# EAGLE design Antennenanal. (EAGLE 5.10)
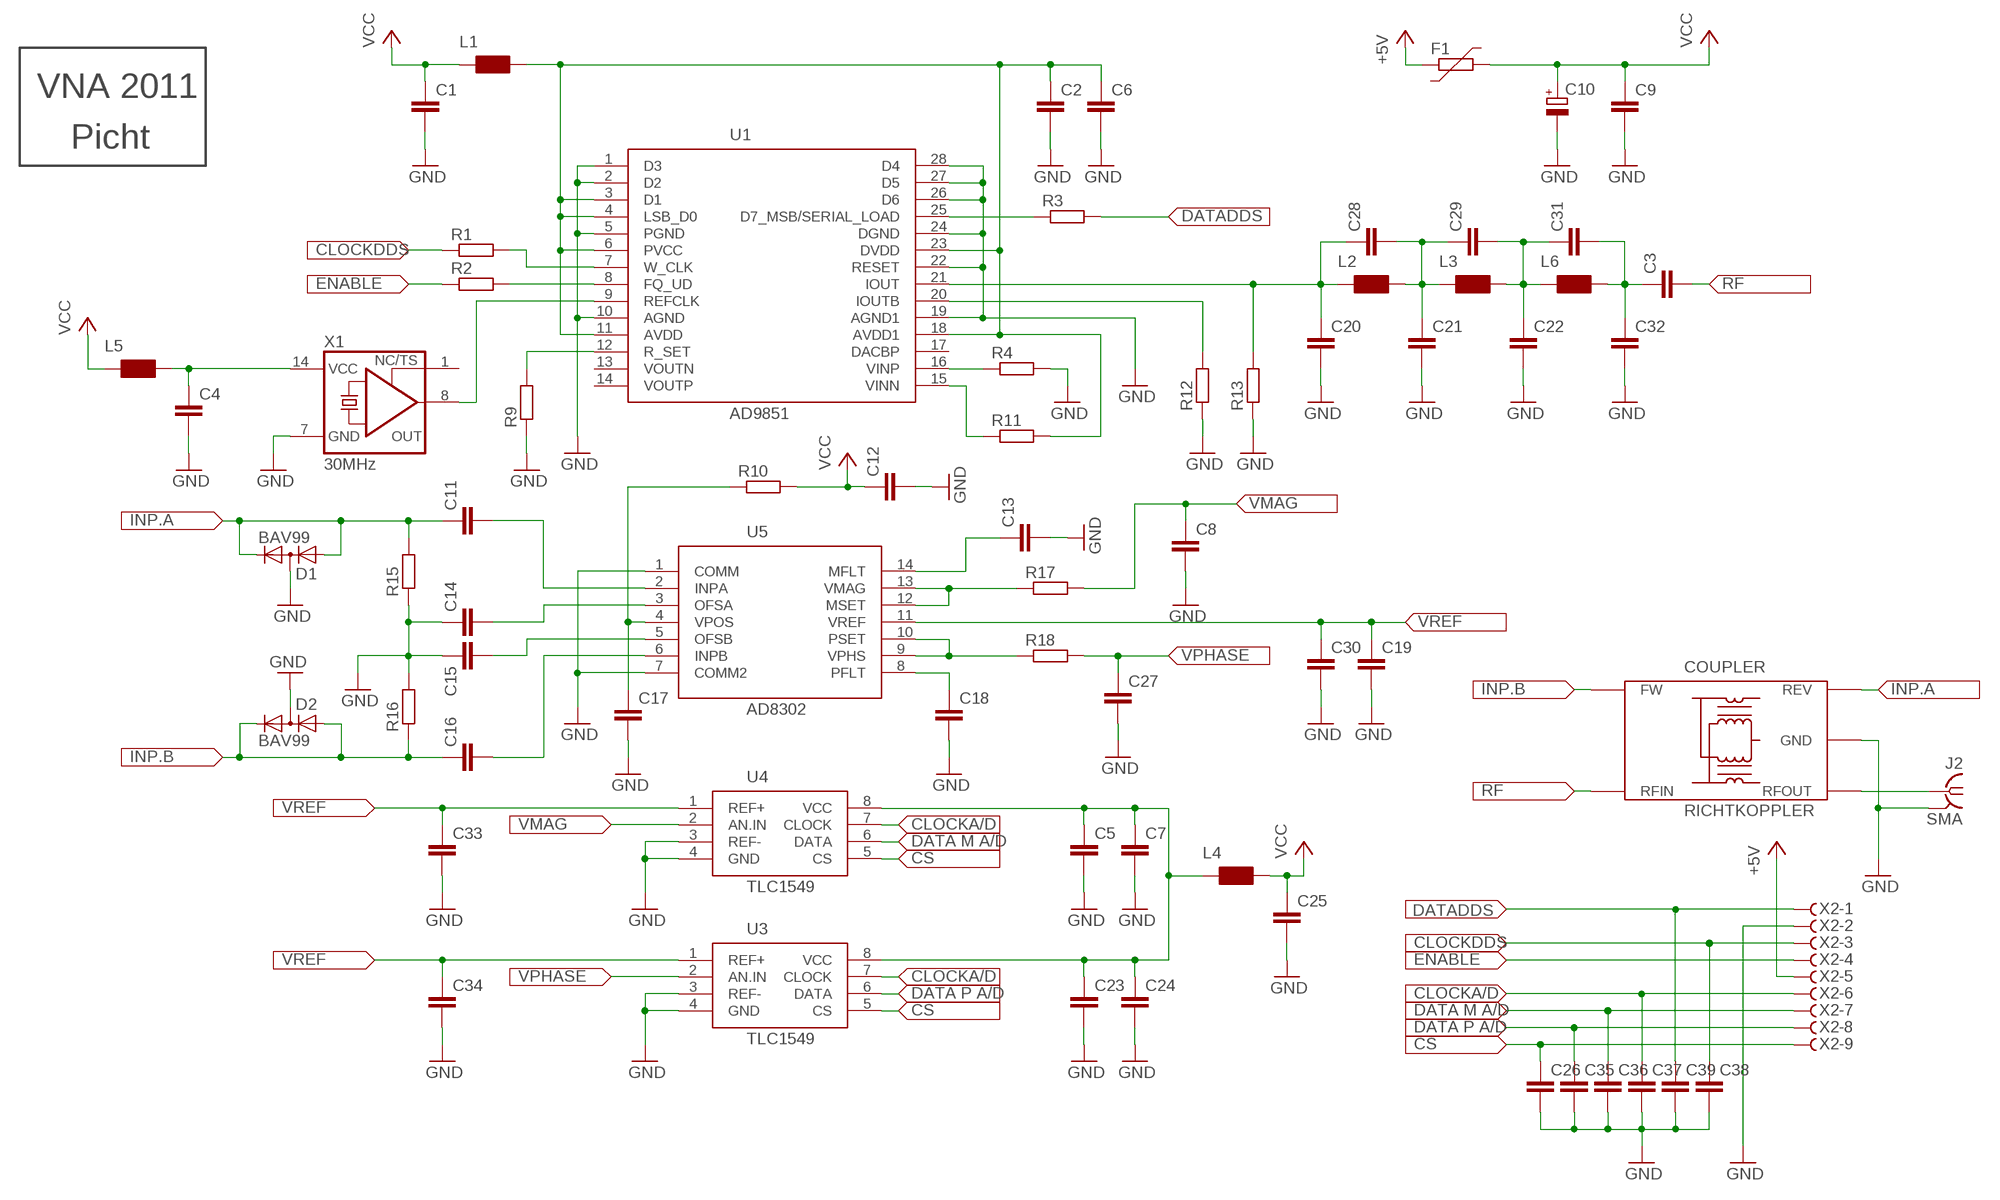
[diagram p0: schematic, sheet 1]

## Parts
C1  C-EUC0805  [C0805]
C2  C-EUC0805  [C0805]
C3  C-EUC0805  [C0805]
C4  C-EUC0805  [C0805]
C5  C-EUC0805  [C0805]
C6  C-EUC0805  [C0805]
C7  C-EUC0805  [C0805]
C8  C-EUC0805  [C0805]
C9  C-EUC0805  [C0805]
C10  CPOL-EU153CLV-0605  [153CLV-0605]
C11  C-EUC0805  [C0805]
C12  C-EUC0805  [C0805]
C13  C-EUC0805  [C0805]
C14  C-EUC0805  [C0805]
C15  C-EUC0805  [C0805]
C16  C-EUC0805  [C0805]
C17  C-EUC0805  [C0805]
C18  C-EUC0805  [C0805]
C19  C-EUC0805  [C0805]
C20  C-EUC0805  [C0805]
C21  C-EUC0805  [C0805]
C22  C-EUC0805  [C0805]
C23  C-EUC0805  [C0805]
C24  C-EUC0805  [C0805]
C25  C-EUC0805  [C0805]
C26  C-EUC0805  [C0805]
C27  C-EUC0805  [C0805]
C28  C-EUC0805  [C0805]
C29  C-EUC0805  [C0805]
C30  C-EUC0805  [C0805]
C31  C-EUC0805  [C0805]
C32  C-EUC0805  [C0805]
C33  C-EUC0805  [C0805]
C34  C-EUC0805  [C0805]
C35  C-EUC0805  [C0805]
C36  C-EUC0805  [C0805]
C37  C-EUC0805  [C0805]
C38  C-EUC0805  [C0805]
C39  C-EUC0805  [C0805]
COUPLER  RICHTKOPPLER  KOPPLER  [KOPPLER]
D1  BAV99  BAV199  [SOT23]
D2  BAV99  BAV199  [SOT23]
F1  R-EU_0204/2V  [0204V]
J2  SMA  SMA-142-0701-851/861  [J502-ND-142-0701-851/861]
L1  IND.1210  [C1210]
L2  IND.1210  [C1210]
L3  IND.1210  [C1210]
L4  IND.1210  [C1210]
L5  IND.1210  [C1210]
L6  IND.1210  [C1210]
R1  R-EU_M1206  [M1206]
R2  R-EU_M1206  [M1206]
R3  R-EU_M1206  [M1206]
R4  R-EU_M1206  [M1206]
R9  R-EU_R1206  [R1206]
R10  R-EU_R1206  [R1206]
R11  R-EU_M1206  [M1206]
R12  R-EU_M1206  [M1206]
R13  R-EU_M1206  [M1206]
R15  R-EU_R1206  [R1206]
R16  R-EU_R1206  [R1206]
R17  R-EU_R1206  [R1206]
R18  R-EU_R1206  [R1206]
U1  AD9851  AD9851BR  [TSSOP28]
U3  TLC1549  [SO8]
U4  TLC1549  [SO8]
U5  AD8302  AD8202  [TSSOP14]
X1  30MHz  XO-14  [DIL14S]
X2  F09HPS  [F09HP]

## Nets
+5V: F1.1 X2.5
CLOCKA/D: C37.1 U3.7(CLOCK) U4.7(CLOCK) X2.6
CLOCKDDS: C38.1 R1.1 X2.3
CS: C26.1 U3.5(CS) U4.5(CS) X2.9
DATA_M_A/D: C36.1 U4.6(DATA) X2.7
DATA_P_A/D: C35.1 U3.6(DATA) X2.8
DATADDS: C39.1 R3.2 X2.1
ENABLE: R2.1 X2.4
GND: C1.2 C2.2 C4.2 C5.2 C6.2 C7.2 C8.2 C9.2 C10.- C12.2 C13.2 C14.1 C15.1 C17.2 C18.2 C19.2 C20.2 C21.2 C22.2 C23.2 C24.2 C25.2 C26.2 C27.2 C30.2 C32.2 C33.2 C34.2 C35.2 C36.2 C37.2 C38.2 C39.2 COUPLER.P$5(GND) D1.3(AC) D2.3(AC) J2.G@1(GND) R4.2 R9.1 R12.1 R13.1 R15.1 R16.2 U1.1(D3) U1.2(D2) U1.5(PGND) U1.10(AGND) U1.19(AGND1) U1.22(RESET) U1.24(DGND) U1.26(D6) U1.27(D5) U1.28(D4) U3.3(REF-) U3.4(GND) U4.3(REF-) U4.4(GND) U5.1(COMM) U5.7(COMM2) X1.7(GND) X2.2
INP.A: C11.1 COUPLER.P$4(REV) D1.1(A) D1.2(C) R15.2
INP.B: C16.1 COUPLER.P$1(FW) D2.1(A) D2.2(C) R16.1
N$1: R12.2 U1.20(IOUTB)
N$2: R1.2 U1.7(W_CLK)
N$3: R2.2 U1.8(FQ_UD)
N$4: R3.1 U1.25(D7_MSB/SERIAL_LOAD)
N$5: R4.1 U1.16(VINP)
N$6: R11.1 U1.15(VINN)
N$7: R9.2 U1.12(R_SET)
N$8: C20.1 C28.1 L2.2 R13.2 U1.21(IOUT)
N$9: C5.1 C7.1 C23.1 C24.1 L4.2 U3.8(VCC) U4.8(VCC)
N$10: C17.1 R10.1 U5.4(VPOS)
N$11: C11.2 U5.2(INPA)
N$12: C21.1 C28.2 C29.1 L2.1(.) L3.2
N$13: C22.1 C29.2 C31.1 L3.1(.) L6.2
N$14: C3.1 C31.2 C32.1 L6.1(.)
N$15: C2.1 C6.1 L1.1(.) R11.2 U1.3(D1) U1.4(LSB_D0) U1.6(PVCC) U1.11(AVDD) U1.18(AVDD1) U1.23(DVDD)
N$16: U1.9(REFCLK) X1.8(OUT)
N$17: C4.1 L5.1(.) X1.14(VCC)
N$18: C13.1 U5.14(MFLT)
N$19: C16.2 U5.6(INPB)
N$20: C18.1 U5.8(PFLT)
N$21: R17.1 U5.12(MSET) U5.13(VMAG)
N$22: COUPLER.P$3(RFOUT) J2.1
N$23: C14.2 U5.3(OFSA)
N$24: R18.1 U5.9(VPHS) U5.10(PSET)
N$25: C15.2 U5.5(OFSB)
RF: C3.2 COUPLER.P$2(RFIN)
VCC: C1.1 C9.1 C10.+ C12.1 C25.1 F1.2 L1.2 L4.1(.) L5.2 R10.2
VMAG: C8.1 R17.2 U4.2(AN.IN)
VPHASE: C27.1 R18.2 U3.2(AN.IN)
VREF: C19.1 C30.1 C33.1 C34.1 U3.1(REF+) U4.1(REF+) U5.11(VREF)
Unconnected: U1.13(VOUTN) U1.14(VOUTP) U1.17(DACBP) X1.1(TS)

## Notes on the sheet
- VNA 2011
- U1
- Picht
- AD9851

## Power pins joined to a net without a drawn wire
GND: J2.G@2(GND) J2.G@3(GND) J2.G@4(GND)

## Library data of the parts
C1-C9 C11-C39 = rcl:C-EU: CAPACITOR, European symbol
C10 = rcl:CPOL-EU: POLARIZED CAPACITOR, European symbol
COUPLER = Koppler:KOPPLER
D1 D2 = diode:BAV199: DIODE low-leakage double diode
F1 R1-R4 R9-R13 R15-R18 = rcl:R-EU_: RESISTOR, European symbol
J2 = con-coax:SMA-: SMA 50 Ohm End Launch Jack Receptacle - Round Contact Johnson Components Source: www.johnsoncomponents.com .. J502-ND.pdf
L1-L6 = Ind.1210:IND.1210
U1 = ad9851:AD9851: DDS
U3 U4 = TLC1549:TLC1549
U5 = AD8302:AD8202
X1 = crystal:XO-: CRYSTAL
X2 = con-subd:F09?S: SUB-D

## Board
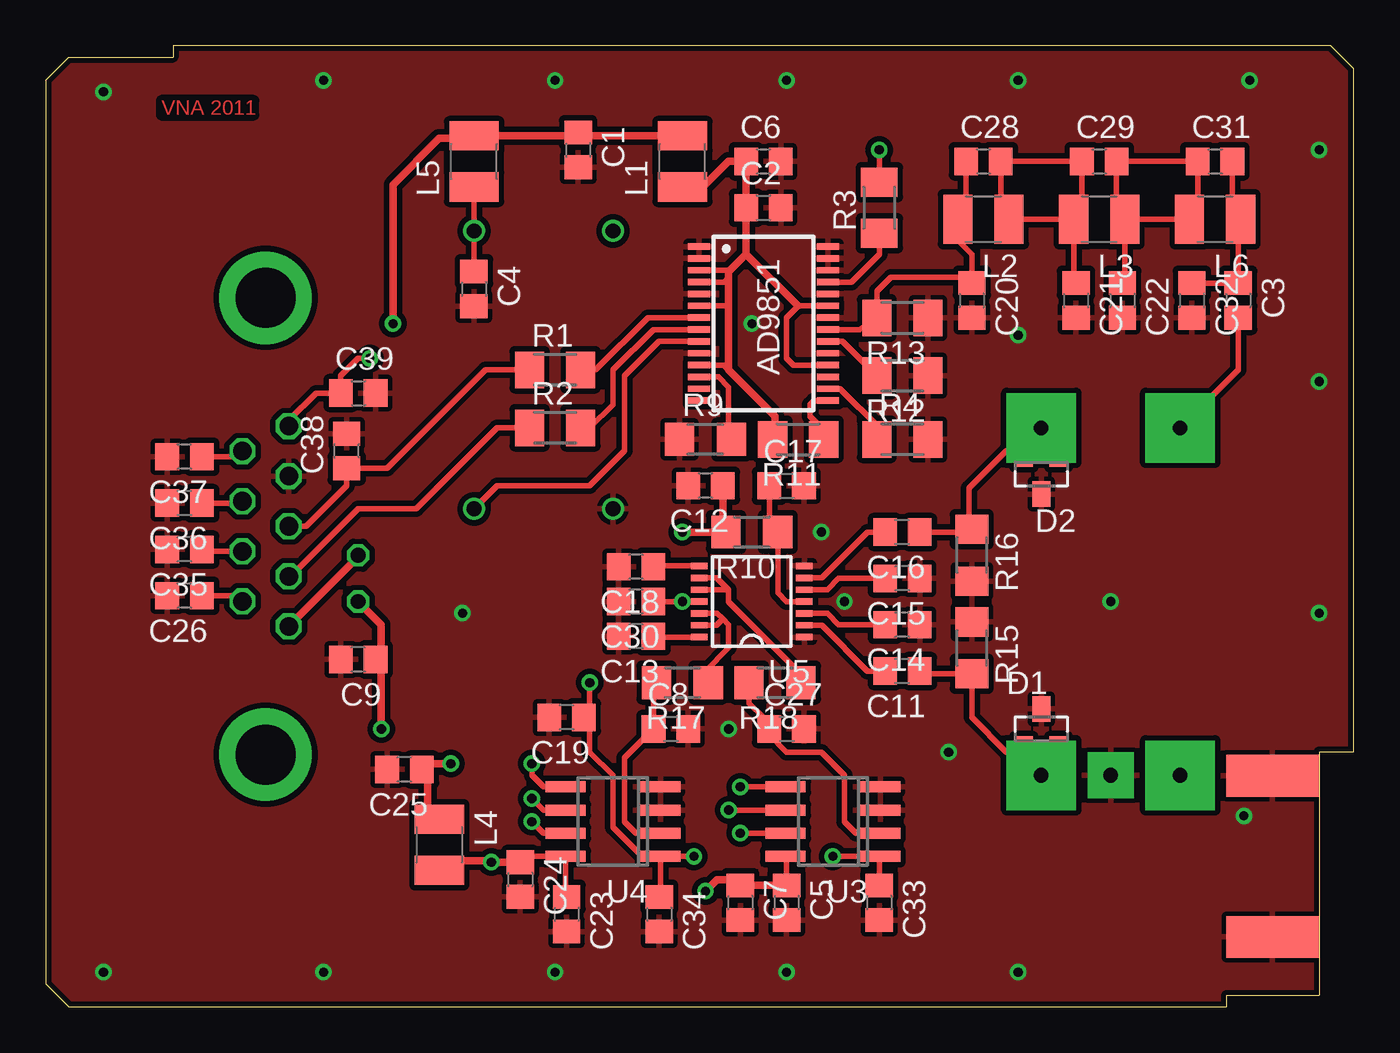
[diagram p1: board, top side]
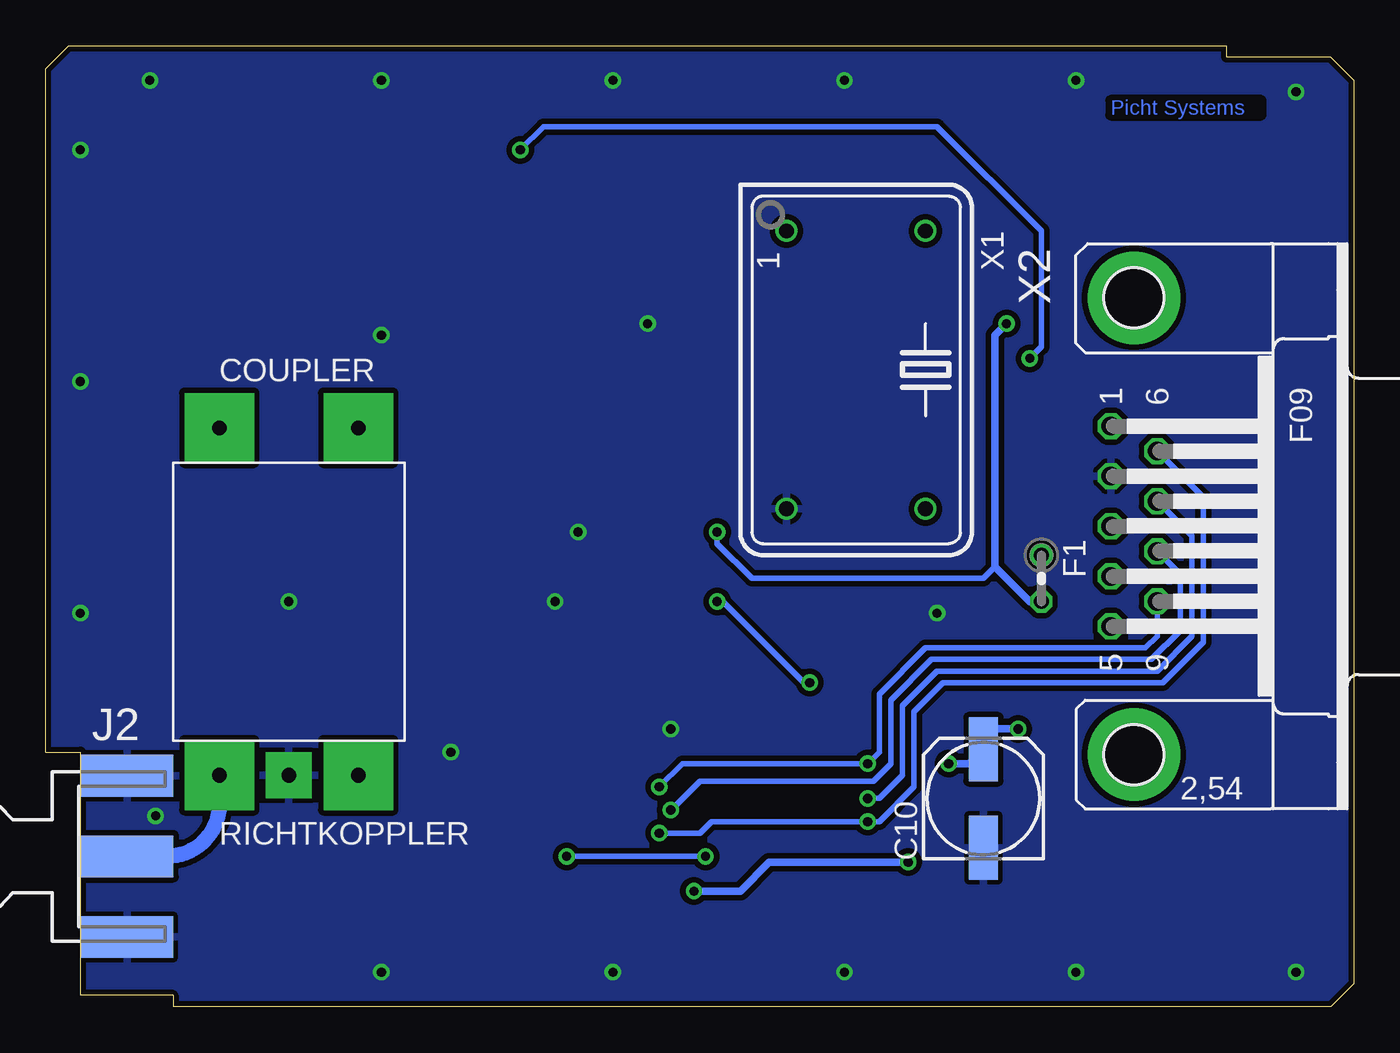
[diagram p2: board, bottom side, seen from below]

Size 71.75 x 52.7 mm. Coordinates in mm from the lower left corner, seen from the top.
Outline: 71.74,51.42 71.74,13.97 69.85,13.97 69.85,0.64 64.77,0.64 64.77,0 1.27,0 0,1.27 0,50.8 1.27,52.07 6.99,52.07 6.99,52.7
Outline: 71.75,51.44 70.48,52.7 6.99,52.7
Copper layers (1*16): Top 0.035mm / dielectric 1.5mm / Bottom 0.035mm
Design rules "ZWILLING": minimum track width 0.2mm, minimum drill 0.5mm, track to track 0.2mm, track to pad 0.2mm, pad to pad 0.15mm, via to via 0.2mm, smd to smd 0mil, copper to edge 0.2mm, drill to drill 0.2mm, minimum pad ring 0.2mm, minimum via ring 0.2mm, stop-mask expansion 0.1mm, vias tented up to drill 0mil, thermal gap 10mil

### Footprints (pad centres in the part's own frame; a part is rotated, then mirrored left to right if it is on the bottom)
C0805 = smd 1.3 x 1.5: 1 -0.95,0; 2 0.95,0
153CLV-0605 = smd 3.5 x 1.6: + 2.7,0; - -2.7,0
KOPPLER = drill 0.8 pad 3.81 square: P$1 3.81,9.525; P$2 -3.81,9.525; P$3 -3.81,-9.525; P$4 3.81,-9.525 | drill 0.8 pad 2.54 square: P$5 0,-9.525
SOT23 = smd 1 x 1.4: 1 -0.95,-1.1; 2 0.95,-1.1; 3 0,1.1
0204V = drill 0.813 octagon: 1 -1.27,0; 2 1.27,0
J502-ND-142-0701-851/861 = smd 5.08 x 2.286: 1 2.565,0; G@1 2.565,4.42; G@2 2.565,-4.42 | smd 5.08 x 2.286 bottom: G@3 2.565,4.42; G@4 2.565,-4.42
C1210 = smd 1.6 x 2.7: 1 -1.4,0; 2 1.4,0
M1206 = smd 1.6 x 2: 1 -1.4,0; 2 1.4,0
R1206 = smd 1.6 x 1.803: 1 -1.422,0; 2 1.422,0
TSSOP28 = smd 0.35 x 1.2: 1 -5.495,-2.9; 2 -4.845,-2.9; 3 -4.195,-2.9; 4 -3.545,-2.9; 5 -2.895,-2.9; 6 -2.245,-2.9; 7 -1.595,-2.9; 8 -0.945,-2.9; 9 -0.295,-2.9; 10 0.355,-2.9; 11 1.005,-2.9; 12 1.655,-2.9; 13 2.305,-2.9; 14 2.955,-2.9; 15 2.955,4.17; 16 2.305,4.17; 17 1.655,4.17; 18 1.005,4.17; 19 0.355,4.17; 20 -0.295,4.17; 21 -0.945,4.17; 22 -1.595,4.17; 23 -2.245,4.17; 24 -2.895,4.17; 25 -3.545,4.17; 26 -4.195,4.17; 27 -4.845,4.17; 28 -5.495,4.17
SO8 = smd 0.6 x 2.2: 1 -1.905,-2.6; 2 -0.635,-2.6; 3 0.635,-2.6; 4 1.905,-2.6; 5 1.905,2.6; 6 0.635,2.6; 7 -0.635,2.6; 8 -1.905,2.6
TSSOP14 = smd 0.9 x 0.35: 1 -2.875,1.95; 2 -2.875,1.3; 3 -2.875,0.65; 4 -2.875,0; 5 -2.875,-0.65; 6 -2.875,-1.3; 7 -2.875,-1.95; 8 2.875,-1.95; 9 2.875,-1.3; 10 2.875,-0.65; 11 2.875,0; 12 2.875,0.65; 13 2.875,1.3; 14 2.875,1.95
DIL14S = drill 0.813 round: 1 -7.62,-3.81; 7 7.62,-3.81; 8 7.62,3.81; 14 -7.62,3.81
F09HP = drill 1.016 octagon: 1 -5.486,-1.27; 2 -2.743,-1.27; 3 0,-1.27; 4 2.743,-1.27; 5 5.486,-1.27; 6 -4.115,1.27; 7 -1.372,1.27; 8 1.372,1.27; 9 4.115,1.27 | drill 3.302 pad 5.08 round: G1 -12.522,0; G2 12.522,0

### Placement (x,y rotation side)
C1  29.21,46.99 270 top
C2  39.37,43.81 0 top
C3  65.41,38.73 270 top
C4  23.5,39.37 270 top
C5  40.64,5.71 270 top
C6  39.37,46.35 0 top
C7  38.1,5.71 270 top
C8  34.29,15.24 0 top
C9  17.14,19.05 180 top
C10  20.32,11.43 90 bottom
C11  46.99,18.41 180 top
C12  36.2,28.57 180 top
C13  32.38,20.32 180 top
C14  46.99,20.95 180 top
C15  46.99,23.5 180 top
C16  46.99,26.04 180 top
C17  40.64,28.57 0 top
C18  32.38,24.13 180 top
C19  28.57,15.88 180 top
C20  50.8,38.73 270 top
C21  56.52,38.73 270 top
C22  59.05,38.73 270 top
C23  28.57,5.08 270 top
C24  26.04,6.99 270 top
C25  19.68,13.02 180 top
C26  7.62,22.54 180 top
C27  40.64,15.24 0 top
C28  51.44,46.35 0 top
C29  57.78,46.35 0 top
C30  32.38,22.23 180 top
C31  64.14,46.35 0 top
C32  62.87,38.73 270 top
C33  45.72,5.71 270 top
C34  33.66,5.08 270 top
C35  7.62,25.08 180 top
C36  7.62,27.62 180 top
C37  7.62,30.16 180 top
C38  16.51,30.48 90 top
C39  17.14,33.66 0 top
COUPLER  58.42,22.23 0 bottom
D1  54.61,15.24 0 top
D2  54.61,29.21 180 top
F1  17.14,23.5 270 bottom
J2  69.85,8.26 0 bottom
L1  34.92,46.35 90 top
L2  51.44,43.18 180 top
L3  57.78,43.18 180 top
L4  21.59,8.89 270 top
L5  23.5,46.35 90 top
L6  64.14,43.18 180 top
R1  27.94,34.92 0 top
R2  27.94,31.75 0 top
R3  45.72,43.81 90 top
R4  46.99,31.11 0 top
R9  36.2,31.11 0 top
R10  38.73,26.04 180 top
R11  41.27,31.11 180 top
R12  46.99,34.61 180 top
R13  46.99,37.78 180 top
R15  50.8,19.68 270 top
R16  50.8,24.77 270 top
R17  34.92,17.78 180 top
R18  40.01,17.78 180 top
U1  38.73,36.2 270 top
U3  43.18,10.16 90 top
U4  31.11,10.16 90 top
U5  38.73,22.23 180 top
X1  27.3,34.92 270 bottom
X2  12.06,26.35 270 bottom

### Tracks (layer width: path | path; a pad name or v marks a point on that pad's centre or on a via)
+5V
  Top 0.406: F1.1 17.14,24.68 X2.5
CLOCKA/D  (via drill 0.5)
  Top 0.305: U4.7 27.3,9.53 v26.67,10.16 | v38.1,9.53 U3.7 | C37.1 10.49,30.16 X2.6
  Bottom 0.305: v38.1,9.53 35.88,9.53 35.24,10.16 v26.67,10.16 26.04,10.16 24.13,12.06 24.13,16.19 22.54,17.78 10.48,17.78 8.26,20 8.26,27.94 8.27,27.94 X2.6
CLOCKDDS
  Top 0.305: R1.1 24.13,34.92 18.73,29.53 C38.1 16.51,28.57 14.29,26.35 X2.3
CS  (via drill 0.5)
  Top 0.305: U4.5 27.3,12.06 26.67,12.7 v26.67,13.34 | v38.1,12.06 U3.5 | C26.1 10.49,22.54 X2.9
  Bottom 0.305: v38.1,12.06 36.83,13.34 v26.67,13.34 26.04,13.97 26.04,17.14 23.5,19.68 11.43,19.68 10.79,20.32 X2.9
DATA_M_A/D  (via drill 0.5)
  Top 0.305: U4.6 27.3,10.79 v26.67,11.43 | C36.1 10.69,27.62 X2.7
  Bottom 0.305: v26.67,11.43 26.04,11.43 24.77,12.7 24.77,16.51 22.86,18.41 10.79,18.41 8.89,20.32 8.89,25.82 X2.7
DATA_P_A/D  (via drill 0.5)
  Top 0.305: v37.47,10.79 U3.6 | 8.67,25.3 C35.1 8.67,24.98 X2.8
  Bottom 0.305: v37.47,10.79 35.88,12.38 26.35,12.38 25.4,13.34 25.4,16.83 23.18,19.05 11.11,19.05 9.53,20.64 9.53,23.71 X2.8
DATADDS  (via drill 0.5)
  Top 0.305: v45.72,46.99 R3.2 | v17.78,35.56 17.14,35.56 16.2,34.61 C39.1 14.83,33.66 13.34,32.16 X2.1
  Bottom 0.305: v45.72,46.99 44.45,48.26 22.86,48.26 17.14,42.55 17.14,36.2 v17.78,35.56
ENABLE
  Top 0.305: R2.1 24.77,31.75 20.32,27.3 17.14,27.3 13.45,23.61 X2.4
GND  (via drill 0.5)
  other vias: 38.73,37.47 42.55,26.04 3.17,50.16 15.24,50.8 66.04,50.8 69.85,21.59 53.34,36.83 15.24,1.91 22.86,21.59 3.17,1.91 49.53,13.97 69.85,46.99 37.47,15.24 43.81,22.23 58.42,22.23 27.94,50.8 40.64,50.8 53.34,50.8 69.85,34.29 27.94,1.91 40.64,1.91 53.34,1.91 65.72,10.48
  pour Top (isolate 0.305): -1.27,52.7 71.75,52.7 71.75,-1.27 -1.27,-0.64
  pour Bottom (isolate 0.305): -1.27,52.7 71.75,52.7 72.39,-0.64 -0.64,-0.64
INP.A
  Top 0.305: C11.1 48.09,18.26 R15.2 50.8,15.88 52.7,13.97 53.34,13.97 | 53.34,13.97 53.34,14.46 D1.1 | 53.34,13.97 COUPLER.P$4 55.56,13.65 D1.2
INP.B
  Top 0.305: C16.1 50.65,26.04 R16.1 50.65,26.67 50.65,28.42 52.7,30.48 52.85,30.48 | 52.85,30.48 D2.2 53.66,30.8 COUPLER.P$1 | 52.85,30.48 53.34,30.48 COUPLER.P$1 | COUPLER.P$1 55.24,31.11 55.24,29.99 D2.1
N$1
  Top 0.305: U1.20 43.71,36.49 R12.2
N$2
  Top 0.305: U1.7 33.03,37.79 30.16,34.92 R1.2
N$3
  Top 0.305: U1.8 33.33,37.14 31.11,34.92 31.11,33.02 29.84,31.75 R2.2
N$4
  Top 0.305: U1.25 44.19,39.74 45.72,41.27 R3.1
N$5
  Top 0.305: U1.16 43.58,33.89 45.72,31.75 45.72,31.25 R4.1
N$6
  Top 0.305: U1.15 42.13,33.24 41.91,33.02 41.91,32.38 42.55,31.75 42.55,31.25 R11.1
N$7
  Top 0.305: U1.12 36.9,34.54 37.47,33.97 37.47,31.27 R9.2
N$8
  Top 0.305: R13.2 45.59,38.4 | U1.21 44.63,37.14 R13.2 | R13.2 45.59,39.24 46.35,40.01 50.48,40.01 C20.1 50.8,41.27 49.53,42.55 L2.2 50.48,43.63 C28.1
N$9  (via drill 0.5)
  Top 0.305: C23.1 28.52,6.09 U4.8 26.36,8.26 C24.1 | 40.33,6.35 C5.1 40.64,8.2 U3.8
  Top 0.406: L4.2 22.35,8 24.07,8 v24.45,7.94 C24.1 | C7.1 37.78,6.35 37.78,6.67 | C7.1 C5.1 | v36.2,6.35 36.83,6.99 37.78,6.99 C7.1
  Bottom 0.406: v36.2,6.35 33.66,6.35 32.07,7.94 v24.45,7.94
N$10
  Top 0.305: C17.1 39.69,26.5 R10.1 40.16,22.71 40.64,22.23 U5.4
N$11
  Top 0.305: U5.2 42.58,20.93 45.09,18.41 C11.2
N$12
  Top 0.305: L3.2 56.38,39.81 C21.1 | L3.2 56.84,43.63 C29.1 C28.2 52.39,44.45 | L2.1 L3.2
N$13
  Top 0.305: 63.12,43.56 L6.2 L3.1 | L3.1 59.19,39.81 C22.1 | L3.1 58.73,43.63 C29.2 | 63.19,43.63 C31.1 59.37,46.35
  Top 0.406: 63.12,43.56 63.19,43.63
N$14
  Top 0.305: 65.72,43.5 66.04,43.18 | 65.72,43.5 65.53,43.31 L6.1 65.41,43.05 C3.1 C32.1 | C31.2 65.08,44.13 65.72,43.5
N$15
  Top 0.305: 37.53,40.39 U1.3 | 37.47,38.44 U1.6 | U1.11 37.2,35.19 37.47,34.92 | U1.23 41.26,38.44 41.27,38.42 40.64,37.78 40.64,35.56 41.01,35.19 U1.18 | U1.4 37.2,39.74 37.47,40.01
  Top 0.406: C2.1 38.35,43.88 | 38.42,41.27 C2.1 | R11.2 40.01,31.25 40.01,32.38 37.47,34.92 37.47,38.44 37.47,40.01 37.47,40.32 37.53,40.39 38.42,41.27 | 38.42,41.27 41.26,38.44 | L1.1 36.06,44.95 37.47,46.35 C6.1 C2.1
N$16
  Top 0.305: U1.9 33.63,36.49 31.75,34.61 31.75,30.48 29.84,28.57 24.77,28.57 X1.8
N$17
  Top 0.305: C4.1 X1.14 L5.1
N$18
  Top 0.305: U5.14 33.38,20.27 C13.1
N$19
  Top 0.305: U5.6 42.58,23.52 45.09,26.04 C16.2
N$20
  Top 0.305: U5.8 33.38,24.18 C18.1
N$21
  Top 0.305: R17.1 36.2,17.78 36.2,18.41 37.47,19.68 37.47,20.95 37.15,21.27 | 37.15,21.27 36.83,21.59 35.88,21.59 U5.12 | U5.13 36.8,20.93 37.15,21.27
N$22
  Bottom 0.813: COUPLER.P$3 62.23,11.11 arc90 65.09,8.26 J2.1
N$23
  Top 0.305: U5.3 42.88,21.57 43.5,20.95 C14.2
N$24
  Top 0.305: 37.47,22.86 35.88,22.86 U5.10 | U5.9 36.8,23.52 37.47,22.86 | 37.47,22.86 37.47,22.23 41.27,18.41 41.27,17.93 R18.1
N$25
  Top 0.305: U5.5 42.88,22.88 43.5,23.5 C15.2
RF
  Top 0.305: C3.2 65.41,34.92 COUPLER.P$2
VCC  (via drill 0.5)
  Top 0.406: C12.1 37.15,26.2 R10.2 v34.92,26.04 | 29.02,47.76 L5.2 23.36,47.62 21.59,47.62 19.05,45.09 v19.05,37.47 | 29.02,47.76 C1.1 | 29.02,47.76 L1.2 | 21.91,10.61 L4.1 22.09,10.16 21.59,10.16 21.91,10.47 21.91,10.61 | F1.2 18.41,20.95 18.41,19.37 C9.1 18.41,18.73 v18.41,15.24 | 21.91,10.61 21.14,10.61 20.95,10.79 20.95,12.38 C25.1 | C25.1 20.95,12.7 | C25.1 20.95,13.34 v22.23,13.34
  Bottom 0.305: v34.92,26.04 34.92,25.4 33.02,23.5 20.32,23.5 19.68,24.13
  Bottom 0.406: F1.2 17.78,22.23 19.68,24.13 19.68,36.83 v19.05,37.47 | v22.23,13.34 21.11,13.34 C10.+ 20.32,15.24 v18.41,15.24
VMAG
  Top 0.305: U4.2 32.38,9.53 31.75,10.16 31.75,13.65 C8.1 33.34,17.62 R17.2
VPHASE
  Top 0.305: R18.2 38.58,16.66 39.37,15.88 39.37,15.56 C27.1 39.69,14.92 40.64,13.97 42.55,13.97 43.81,12.7 43.81,10.16 44.45,9.53 U3.2
VREF  (via drill 0.5)
  Top 0.305: C30.1 v34.92,22.23 U5.11 | v43.18,8.26 U3.1 45.72,8.2 C33.1 | U4.1 32.7,8.26 31.11,9.84 31.11,12.7 29.84,13.97 29.84,15.55 C19.1 29.84,16.2 v29.84,17.78 | U4.1 33.72,6.09 C34.1 | U4.1 v35.56,8.26
  Bottom 0.305: v35.56,8.26 v43.18,8.26 | v34.92,22.23 34.6,22.23 30.16,17.78 v29.84,17.78

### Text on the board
Top: VNA 2011
Bottom: Picht Systems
